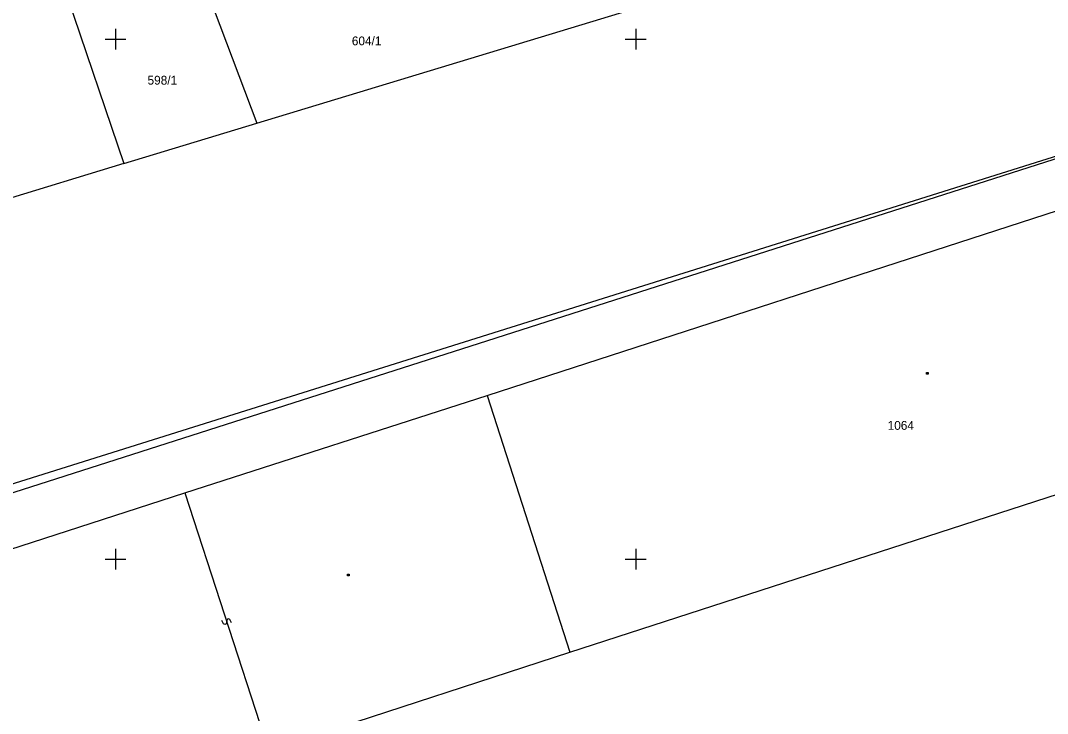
# Model space of a CAD drawing. Extents: x -493352 to -492964, y -1127001 to -1126712.
# Drawn here: x -493295.5 to -493236.3, y -1126808.9 to -1126768.9 of the extents above; entities that cross this region are included whole.
import ezdxf

# ---------------------------------------------------------------- set-up
doc = ezdxf.new("R2010")
doc.units = 0
doc.layers.add('katastrální mapa', color=7, linetype='Continuous')
doc.layers.add('síť', color=7, linetype='Continuous')

msp = doc.modelspace()

# ---------------------------------------------------------------- linework, layer by layer
at = {"layer": 'katastrální mapa'}
for p, q in [((-493293.17, -1126766.39), (-493289.51, -1126777.18)), ((-493281.85, -1126774.85), (-493254.59, -1126766.56)), ((-493284.31, -1126768.32), (-493281.85, -1126774.85)), ((-493352.28, -1126813.34), (-493214.46, -1126770.06)), ((-493344.53, -1126811.74), (-493217.62, -1126771.08)), ((-493289.51, -1126777.18), (-493281.85, -1126774.85)), ((-493268.56, -1126790.55), (-493220.89, -1126775.09)), ((-493289.51, -1126777.18), (-493296.7, -1126779.37)), ((-493243.23, -1126789.24), (-493243.14, -1126789.24)), ((-493243.23, -1126789.33), (-493243.23, -1126789.24)), ((-493243.14, -1126789.33), (-493243.23, -1126789.33)), ((-493243.14, -1126789.24), (-493243.14, -1126789.33)), ((-493263.8, -1126805.38), (-493216.16, -1126789.9)), ((-493286, -1126796.18), (-493268.56, -1126790.55)), ((-493268.56, -1126790.55), (-493263.8, -1126805.38)), ((-493349.92, -1126816.81), (-493286, -1126796.18)), ((-493286, -1126796.18), (-493281.17, -1126811.03)), ((-493276.62, -1126800.87), (-493276.53, -1126800.87)), ((-493276.62, -1126800.96), (-493276.62, -1126800.87)), ((-493276.53, -1126800.96), (-493276.62, -1126800.96)), ((-493276.53, -1126800.87), (-493276.53, -1126800.96)), ((-493283.77, -1126803.73), (-493283.86, -1126803.54)), ((-493283.69, -1126803.77), (-493283.77, -1126803.73)), ((-493283.63, -1126803.75), (-493283.69, -1126803.77)), ((-493283.59, -1126803.67), (-493283.63, -1126803.75)), ((-493283.58, -1126803.54), (-493283.59, -1126803.67)), ((-493283.54, -1126803.46), (-493283.58, -1126803.54)), ((-493283.48, -1126803.44), (-493283.54, -1126803.46)), ((-493283.4, -1126803.48), (-493283.48, -1126803.44)), ((-493283.31, -1126803.67), (-493283.4, -1126803.48)), ((-493281.17, -1126811.03), (-493263.8, -1126805.38))]:
    msp.add_line(p, q, dxfattribs=at)
at = {"layer": 'síť'}
for p, q in [((-493290, -1126769.4), (-493290, -1126770.6)), ((-493260, -1126769.4), (-493260, -1126770.6)), ((-493290.6, -1126770), (-493289.4, -1126770)), ((-493260.6, -1126770), (-493259.4, -1126770)), ((-493290, -1126799.4), (-493290, -1126800.6)), ((-493260, -1126799.4), (-493260, -1126800.6)), ((-493290.6, -1126800), (-493289.4, -1126800)), ((-493260.6, -1126800), (-493259.4, -1126800))]:
    msp.add_line(p, q, dxfattribs=at)

# ---------------------------------------------------------------- texts
at = {"layer": 'katastrální mapa'}
for s, p in [('604/1', (-493276.37, -1126770.35)), ('598/1', (-493288.15, -1126772.62)), ('1064', (-493245.47, -1126792.54))]:
    msp.add_text(s, height=0.51, dxfattribs=at).set_placement(p)

doc.saveas('drawing.dxf')
